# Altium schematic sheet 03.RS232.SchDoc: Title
size A4; Team: Team Platform; Date: *******; ApprovedBy: *******; CheckedBy: None; Author: *******; CompanyName: *******; DrawnBy: Jaden; Engineer: *******; Organization: *******; Address1: *******; Address2: *******; Address3: *******; Address4: *******; DocumentNumber: 4; Revision: *******; SheetNumber: 4; SheetTotal: 6
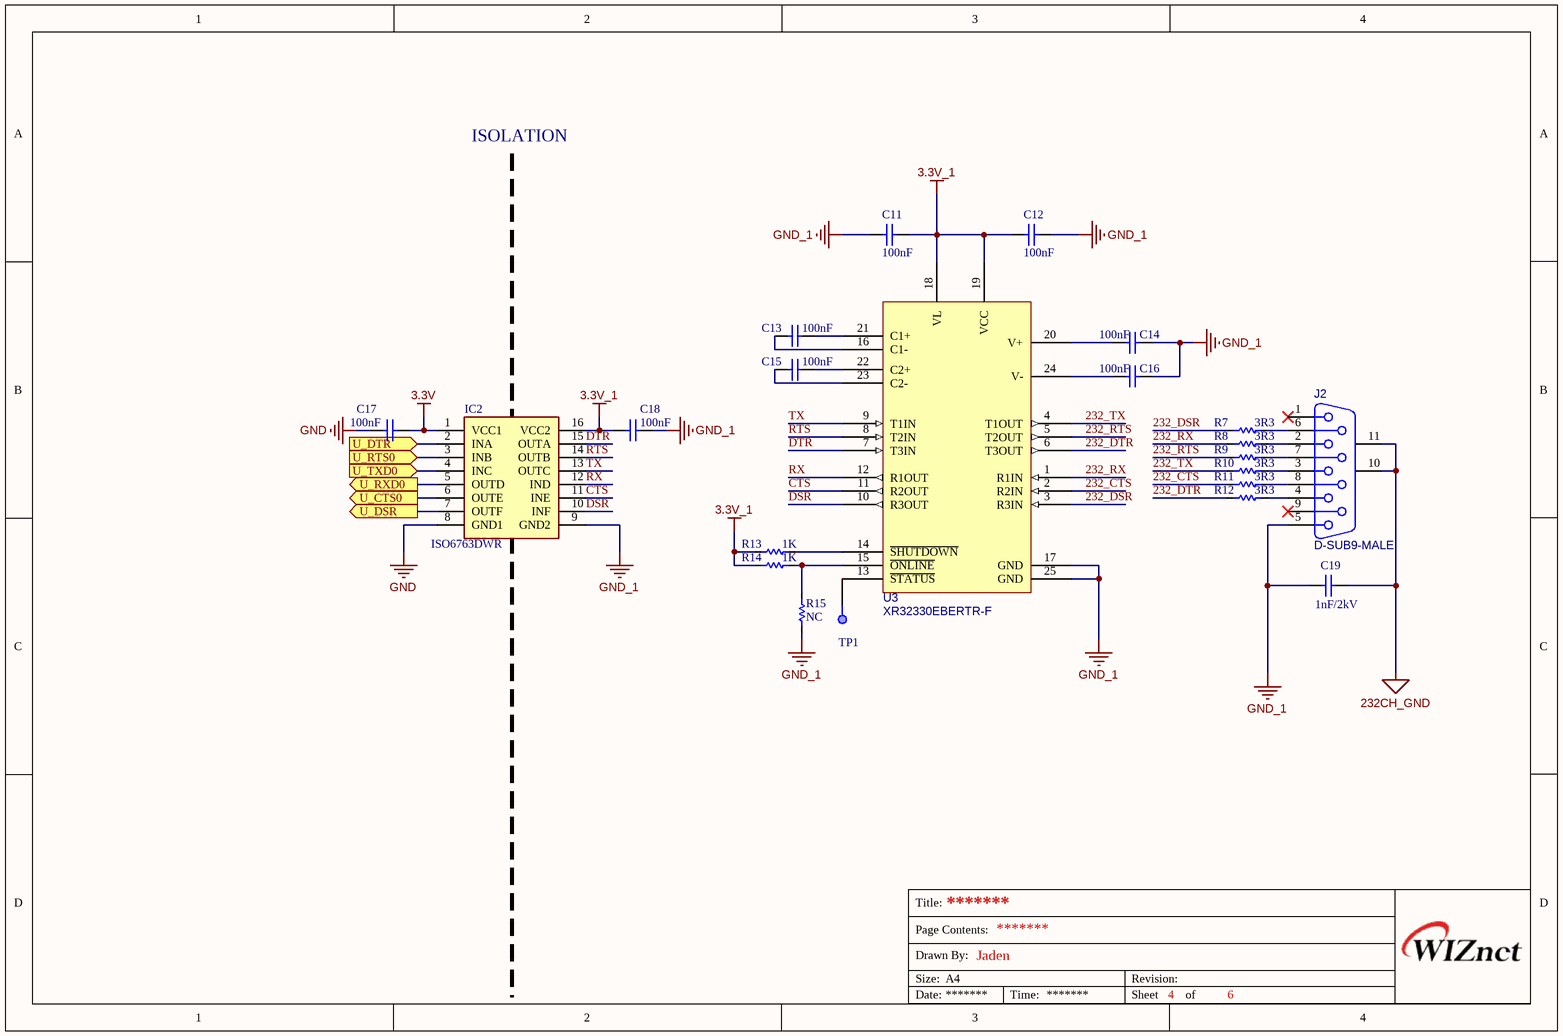
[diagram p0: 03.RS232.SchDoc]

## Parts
C11  100nF  [CAP-0402]
C12  100nF  [CAP-0402]
C13  100nF  [CAP-0402]
C14  100nF  [CAP-0402]
C15  100nF  [CAP-0402]
C16  100nF  [CAP-0402]
C17  100nF  [CAP-0402]
C18  100nF  [CAP-0402]
C19  1nF/2kV  [CAP-1808]
IC2  ISO6763DWR  [SOIC127P1030X265-16N]
J2  D-SUB9-MALE  [D-SUB9-MALE]
R7  3R3  [RES-0402]
R8  3R3  [RES-0402]
R9  3R3  [RES-0402]
R10  3R3  [RES-0402]
R11  3R3  [RES-0402]
R12  3R3  [RES-0402]
R13  1K  [RES-0402]
R14  1K  [RES-0402]
R15  NC  [RES-0402]
TP1  TPS  [TPS]  (value not drawn)  (no BOM)
U3  XR32330EBERTR-F  [QFN24(0.5/4X4)]

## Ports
U_CTS0 (out), U_DSR (out), U_DTR (in), U_RTS0 (in), U_RXD0 (out), U_TXD0 (in)

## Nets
3.3V: C17.1 IC2.1(VCC1)
3.3V_1: C11.2 C12.1 C18.2 IC2.16(VCC2) R13.1 R14.1 U3.18(VL) U3.19(VCC)
232CH_GND: C19.1 J2.10(MH1) J2.11(MH2)
GND: C17.2 IC2.8(GND1)
GND_1: C11.1 C12.2 C14.1 C16.1 C18.1 C19.2 IC2.9(GND2) J2.5 R15.1 U3.17(GND) U3.25(GND)
232_CTS: R11.1 U3.2(R2IN)
232_DSR: R7.1 U3.3(R3IN)
232_DTR: R12.1 U3.6(T3OUT)
232_RTS: R9.1 U3.5(T2OUT)
232_RX: R8.1 U3.1(R1IN)
232_TX: R10.1 U3.4(T1OUT)
CTS: IC2.11(INE) U3.11(R2OUT)
DSR: IC2.10(INF) U3.10(R3OUT)
DTR: IC2.15(OUTA) U3.7(T3IN)
RTS: IC2.14(OUTB) U3.8(T2IN)
RX: IC2.12(IND) U3.12(R1OUT)
TX: IC2.13(OUTC) U3.9(T1IN)
U_CTS0: IC2.6(OUTE) ; port U_CTS0
U_DSR: IC2.7(OUTF) ; port U_DSR
U_DTR: IC2.2(INA) ; port U_DTR
U_RTS0: IC2.3(INB) ; port U_RTS0
U_RXD0: IC2.5(OUTD) ; port U_RXD0
U_TXD0: IC2.4(INC) ; port U_TXD0
NetC13_1: C13.1 U3.21(C1+)
NetC13_2: C13.2 U3.16(C1-)
NetC14_2: C14.2 U3.20(V+)
NetC15_1: C15.1 U3.22(C2+)
NetC15_2: C15.2 U3.23(C2-)
NetC16_2: C16.2 U3.24(V-)
NetJ2_2: J2.2 R8.2
NetJ2_3: J2.3 R10.2
NetJ2_4: J2.4 R12.2
NetJ2_6: J2.6 R7.2
NetJ2_7: J2.7 R9.2
NetJ2_8: J2.8 R11.2
NetR13_2: R13.2 U3.14(~{SHUTDOWN})
NetR14_2: R14.2 R15.2 U3.15(~{ONLINE})
NetTP1_1: TP1.1 U3.13(~{STATUS})

Not connected (* = marked no-connect by the designer): J2 1* 9*

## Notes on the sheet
- ISOLATION

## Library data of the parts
C11-C18 = CAP-0402: MLCC-0402(1005)
C19 = CAP-1808: MLCC-1808(4520)
IC2 = ISO6763DWR: Integrated Circuit; Manufacturer_Name: Texas Instruments
J2 = D-SUB9-MALE: D-SUB-9, MALE,  Right Angle; PackageDocument: O; Positions: 9; Gender: Receptacle
R7-R15 = RES-0402: Chip Resistor 0402(1005)
TP1 = TPS: Test_point; Manufacturer: Wurth Elektronik; Part Number: 61300211121; Rated Current: 3A; Gender: Male; Withstanding Voltage: 500VAC; Working Voltage: 250VAC; Pitch: 2.54mm; Contact Resistance: 20mOhm; Row Number: Single; Pin Number: 2
U3 = XR32330EBERTR-F: 3-Driver/3-Receiver RS232 Transceiver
